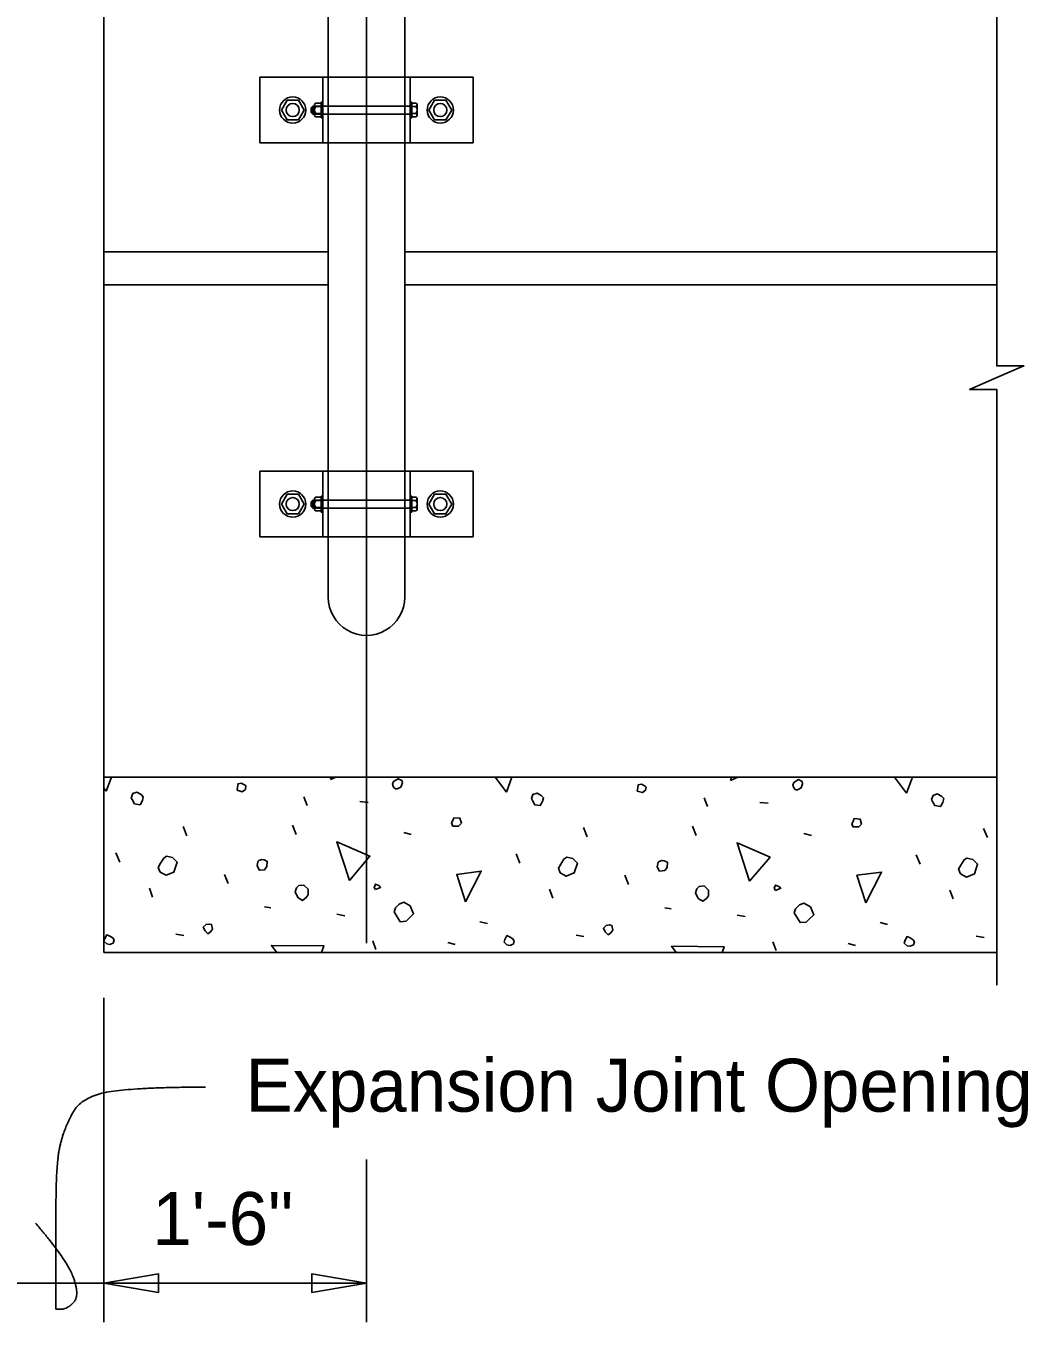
# Model space of a CAD drawing. Extents: x 0 to 41.2, y 0 to 26.
# Drawn here: x 27.279 to 31.095, y 12.062 to 16.996 of the extents above; entities that cross this region are included whole.
import ezdxf

# ---------------------------------------------------------------- set-up
doc = ezdxf.new("R2010")
doc.units = 0
for name, color, linetype in [('CL_Major', 7, 'Continuous'), ('Dimension', 7, 'Continuous'), ('Miscellaneous', 7, 'Continuous'), ('SteelMisc', 7, 'Continuous'), ('SteelMisc_h', 7, 'Continuous'), ('SupstrConc', 7, 'Continuous'), ('TextStructures', 7, 'Continuous')]:
    doc.layers.add(name, color=color, linetype=linetype)

msp = doc.modelspace()

# ---------------------------------------------------------------- linework, layer by layer
at = {"layer": 'CL_Major'}
for p, q in [((28.5763, 25.5043), (28.5763, 13.5039)), ((28.5763, 12.6814), (28.5763, 12.062))]:
    msp.add_line(p, q, dxfattribs=at)
at = {"layer": 'Dimension'}
for p, q in [((27.5763, 13.2961), (27.5763, 12.062)), ((28.5763, 12.21), (26.2429, 12.21))]:
    msp.add_line(p, q, dxfattribs=at)
msp.add_lwpolyline([(30.9761, 17.1361), (30.9761, 15.7022), (31.0795, 15.7022), (30.9761, 15.6572), (30.8728, 15.6122), (30.9761, 15.6122), (30.9761, 13.3448)], dxfattribs=at)
for points in [[(27.5762, 12.2101), (27.7845, 12.1748), (27.7845, 12.2454)], [(28.5762, 12.2101), (28.368, 12.2454), (28.368, 12.1748)]]:
    msp.add_lwpolyline(points, close=True, dxfattribs=at)
msp.add_open_spline([(27.3159, 12.4385), (27.434, 12.3022), (27.4854, 12.1629), (27.437, 12.1114), (27.3939, 12.1114), (27.3939, 12.1114), (27.3939, 12.3628), (27.3939, 12.6656), (27.4249, 12.8019), (27.4975, 12.926), (27.7306, 12.9563), (27.9637, 12.9563)], degree=2, dxfattribs=at)
at = {"layer": 'Miscellaneous'}
for p, q in [((28.3687, 16.6691), (28.3687, 16.6812)), ((28.3744, 16.6691), (28.3744, 16.6812)), ((28.3687, 15.1691), (28.3687, 15.1812)), ((28.3744, 15.1691), (28.3744, 15.1812)), ((29.525, 14.1361), (29.5261, 14.1359)), ((28.3505, 14.0281), (28.3382, 14.0617)), ((28.5503, 14.044), (28.5821, 14.0404)), ((29.8743, 14.0245), (29.862, 14.0581)), ((30.0741, 14.0404), (30.1059, 14.0369)), ((27.8927, 13.9132), (27.8785, 13.9485)), ((28.3081, 13.9185), (28.294, 13.9538)), ((28.7182, 13.9255), (28.7465, 13.9185)), ((29.4165, 13.9096), (29.4024, 13.945)), ((29.8319, 13.9149), (29.8178, 13.9503)), ((30.242, 13.922), (30.2703, 13.9149)), ((30.9403, 13.9061), (30.9262, 13.9414)), ((27.6364, 13.8124), (27.6222, 13.8478)), ((29.1602, 13.8089), (29.146, 13.8442)), ((30.684, 13.8053), (30.6698, 13.8407)), ((28.05, 13.7311), (28.0359, 13.7664)), ((29.5738, 13.7275), (29.5597, 13.7629)), ((27.7619, 13.6798), (27.7495, 13.7134)), ((29.2857, 13.6763), (29.2733, 13.7099)), ((30.8095, 13.6727), (30.7971, 13.7063)), ((28.1879, 13.6427), (28.2126, 13.6392)), ((29.7117, 13.6392), (29.7365, 13.6356)), ((28.4637, 13.6144), (28.4937, 13.6091)), ((29.0081, 13.5861), (29.0364, 13.5791)), ((29.9875, 13.6109), (30.0175, 13.6056)), ((30.532, 13.5826), (30.5602, 13.5755)), ((27.8503, 13.5384), (27.8803, 13.5331)), ((29.3741, 13.5349), (29.4041, 13.5296)), ((30.8979, 13.5313), (30.9279, 13.526)), ((28.6122, 13.4801), (28.5998, 13.5136)), ((28.8862, 13.5066), (28.9145, 13.4995)), ((30.136, 13.4765), (30.1236, 13.5101)), ((30.41, 13.503), (30.4383, 13.496))]:
    msp.add_line(p, q, dxfattribs=at)
for points in [[(27.605, 14.1361), (27.5851, 14.0829)], [(28.0836, 14.0864), (28.103, 14.0811), (28.1154, 14.0899), (28.1172, 14.1023), (28.1137, 14.1058), (28.0995, 14.1129), (28.0871, 14.1112), (28.0854, 14.0988), (28.0836, 14.0864)], [(28.4389, 14.1271), (28.4417, 14.1361)], [(28.4591, 14.1361), (28.4389, 14.1271)], [(28.6864, 14.0917), (28.6935, 14.0917), (28.7076, 14.0988), (28.7129, 14.1147), (28.7112, 14.1235), (28.697, 14.1306), (28.6793, 14.12), (28.6758, 14.1094), (28.6793, 14.0988), (28.6864, 14.0917)], [(29.1089, 14.0793), (29.0657, 14.1361)], [(29.1301, 14.1361), (29.1089, 14.0793)], [(29.9627, 14.1235), (29.9666, 14.1361)], [(29.9908, 14.1361), (29.9627, 14.1235)], [(30.2102, 14.0882), (30.2173, 14.0882), (30.2314, 14.0952), (30.2367, 14.1112), (30.235, 14.12), (30.2208, 14.1271), (30.2032, 14.1165), (30.1996, 14.1058), (30.2032, 14.0952), (30.2102, 14.0882)], [(30.6327, 14.0758), (30.5869, 14.1361)], [(30.6553, 14.1361), (30.6327, 14.0758)], [(27.5851, 14.0829), (27.5763, 14.0945)], [(27.6841, 14.051), (27.6929, 14.0351), (27.7141, 14.0316), (27.723, 14.0475), (27.7265, 14.0617), (27.7177, 14.0705), (27.7018, 14.0793), (27.6859, 14.074), (27.6805, 14.0581), (27.6841, 14.051)], [(29.2079, 14.0475), (29.2167, 14.0316), (29.238, 14.0281), (29.2468, 14.044), (29.2503, 14.0581), (29.2415, 14.067), (29.2256, 14.0758), (29.2097, 14.0705), (29.2044, 14.0546), (29.2079, 14.0475)], [(29.6074, 14.0829), (29.6269, 14.0776), (29.6392, 14.0864), (29.641, 14.0988), (29.6375, 14.1023), (29.6233, 14.1094), (29.611, 14.1076), (29.6092, 14.0952), (29.6074, 14.0829)], [(30.7317, 14.044), (30.7406, 14.0281), (30.7618, 14.0245), (30.7706, 14.0404), (30.7741, 14.0546), (30.7653, 14.0634), (30.7494, 14.0723), (30.7335, 14.067), (30.7282, 14.051), (30.7317, 14.044)], [(28.9056, 13.9503), (28.9268, 13.9503), (28.9374, 13.9609), (28.9321, 13.9803), (28.9091, 13.9821), (28.9056, 13.9715), (28.9003, 13.9627), (28.9056, 13.9503), (28.9021, 13.9538)], [(30.4294, 13.9467), (30.4506, 13.9467), (30.4612, 13.9574), (30.4559, 13.9768), (30.433, 13.9786), (30.4294, 13.968), (30.4241, 13.9591), (30.4294, 13.9467), (30.4259, 13.9503)], [(28.5114, 13.7435), (28.4637, 13.8902), (28.5892, 13.8354), (28.5114, 13.7435)], [(30.0352, 13.7399), (29.9875, 13.8866), (30.113, 13.8318), (30.0352, 13.7399)], [(27.7902, 13.7753), (27.8131, 13.7629), (27.8432, 13.7753), (27.8556, 13.8124), (27.8379, 13.8301), (27.8149, 13.8354), (27.8043, 13.8283), (27.7919, 13.8089), (27.7831, 13.793), (27.7902, 13.7753)], [(28.1596, 13.7983), (28.1685, 13.7823), (28.1879, 13.7841), (28.1967, 13.7965), (28.1985, 13.8159), (28.1861, 13.8212), (28.1773, 13.823), (28.1667, 13.8195), (28.1631, 13.8159), (28.1596, 13.7983)], [(29.314, 13.7717), (29.3369, 13.7594), (29.367, 13.7717), (29.3794, 13.8089), (29.3617, 13.8265), (29.3387, 13.8318), (29.3281, 13.8248), (29.3157, 13.8053), (29.3069, 13.7894), (29.314, 13.7717)], [(29.6834, 13.7947), (29.6923, 13.7788), (29.7117, 13.7806), (29.7206, 13.793), (29.7223, 13.8124), (29.7099, 13.8177), (29.7011, 13.8195), (29.6905, 13.8159), (29.687, 13.8124), (29.6834, 13.7947)], [(30.8378, 13.7682), (30.8608, 13.7558), (30.8908, 13.7682), (30.9032, 13.8053), (30.8855, 13.823), (30.8625, 13.8283), (30.8519, 13.8212), (30.8395, 13.8018), (30.8307, 13.7859), (30.8378, 13.7682)], [(28.9533, 13.6621), (28.9198, 13.7664), (29.0134, 13.7788), (28.9533, 13.6621)], [(30.4772, 13.6586), (30.4436, 13.7629), (30.5373, 13.7753), (30.4772, 13.6586)], [(28.3046, 13.6993), (28.3152, 13.678), (28.3329, 13.6674), (28.347, 13.678), (28.3541, 13.6887), (28.3541, 13.7099), (28.3382, 13.7258), (28.3187, 13.724), (28.3099, 13.7152), (28.3046, 13.6993)], [(28.6104, 13.7081), (28.6298, 13.7169), (28.6228, 13.724), (28.6104, 13.7293), (28.6051, 13.7169), (28.6104, 13.7081)], [(29.8284, 13.6957), (29.839, 13.6745), (29.8567, 13.6639), (29.8708, 13.6745), (29.8779, 13.6851), (29.8779, 13.7063), (29.862, 13.7222), (29.8425, 13.7205), (29.8337, 13.7116), (29.8284, 13.6957)], [(30.1342, 13.7046), (30.1537, 13.7134), (30.1466, 13.7205), (30.1342, 13.7258), (30.1289, 13.7134), (30.1342, 13.7046)], [(28.6811, 13.6232), (28.7041, 13.5861), (28.7271, 13.5879), (28.7359, 13.5967), (28.7554, 13.6162), (28.743, 13.6462), (28.7182, 13.6604), (28.7006, 13.6533), (28.6864, 13.6392), (28.6811, 13.6232)], [(30.2049, 13.6197), (30.2279, 13.5826), (30.2509, 13.5844), (30.2597, 13.5932), (30.2792, 13.6126), (30.2668, 13.6427), (30.242, 13.6568), (30.2244, 13.6498), (30.2102, 13.6356), (30.2049, 13.6197)], [(27.9616, 13.5508), (27.9722, 13.5402), (27.9828, 13.5472), (27.9899, 13.5578), (27.9864, 13.5755), (27.9775, 13.5773), (27.9652, 13.5755), (27.9546, 13.5649), (27.9616, 13.5508)], [(29.4854, 13.5472), (29.496, 13.5366), (29.5067, 13.5437), (29.5137, 13.5543), (29.5102, 13.572), (29.5013, 13.5738), (29.489, 13.572), (29.4784, 13.5614), (29.4854, 13.5472)], [(27.5869, 13.5013), (27.5992, 13.4995), (27.6116, 13.5048), (27.6151, 13.5154), (27.6098, 13.5243), (27.5992, 13.5313), (27.5869, 13.5366), (27.5798, 13.5225), (27.5763, 13.5119), (27.5869, 13.5013)], [(29.1107, 13.4977), (29.123, 13.496), (29.1354, 13.5013), (29.139, 13.5119), (29.1337, 13.5207), (29.123, 13.5278), (29.1107, 13.5331), (29.1036, 13.5189), (29.1001, 13.5083), (29.1107, 13.4977)], [(30.6345, 13.4942), (30.6469, 13.4924), (30.6592, 13.4977), (30.6628, 13.5083), (30.6575, 13.5172), (30.6469, 13.5243), (30.6345, 13.5296), (30.6274, 13.5154), (30.6239, 13.5048), (30.6345, 13.4942)], [(28.2346, 13.4695), (28.2144, 13.496), (28.4142, 13.4942), (28.4049, 13.4695)], [(29.7557, 13.4695), (29.7382, 13.4924), (29.938, 13.4907), (29.9301, 13.4695)]]:
    msp.add_lwpolyline(points, dxfattribs=at)
at = {"layer": 'SteelMisc'}
for p, q in [((28.4305, 16.801), (28.4305, 17.2769)), ((28.7221, 16.801), (28.7221, 17.2769)), ((28.1703, 16.801), (28.9823, 16.801)), ((28.1703, 16.551), (28.1703, 16.801)), ((28.4096, 16.801), (28.4096, 16.551)), ((28.743, 16.801), (28.743, 16.551)), ((28.9823, 16.801), (28.9823, 16.551)), ((28.3659, 16.684), (28.3715, 16.6906)), ((28.3659, 16.6663), (28.3659, 16.684)), ((28.3715, 16.6906), (28.3781, 16.6906)), ((28.3715, 16.6607), (28.3715, 16.6906)), ((28.3781, 16.6939), (28.3781, 16.6582)), ((28.3828, 16.689), (28.4031, 16.689)), ((28.383, 16.702), (28.4031, 16.702)), ((28.4031, 16.7063), (28.4031, 16.6457)), ((28.4031, 16.7063), (28.4096, 16.7063)), ((28.4031, 16.702), (28.4031, 16.65)), ((28.7492, 16.7063), (28.7432, 16.7063)), ((28.7492, 16.7063), (28.7492, 16.6457)), ((28.7639, 16.702), (28.7492, 16.702)), ((28.7641, 16.689), (28.7492, 16.689)), ((28.769, 16.6566), (28.769, 16.6955)), ((28.3659, 16.6663), (28.3715, 16.6607)), ((28.3715, 16.6607), (28.3781, 16.6607)), ((28.3828, 16.6631), (28.4031, 16.6631)), ((28.3831, 16.65), (28.4031, 16.65)), ((28.4031, 16.6457), (28.4096, 16.6457)), ((28.7492, 16.6457), (28.7432, 16.6457)), ((28.7641, 16.663), (28.7492, 16.663)), ((28.7639, 16.65), (28.7492, 16.65)), ((28.9823, 16.551), (28.1703, 16.551)), ((28.4305, 16.551), (28.4305, 15.301)), ((28.7221, 16.551), (28.7221, 15.301)), ((28.1703, 15.301), (28.9823, 15.301)), ((28.1703, 15.051), (28.1703, 15.301)), ((28.4096, 15.301), (28.4096, 15.051)), ((28.743, 15.301), (28.743, 15.051)), ((28.9823, 15.301), (28.9823, 15.051)), ((28.383, 15.202), (28.4031, 15.202)), ((28.4031, 15.2063), (28.4031, 15.1457)), ((28.4031, 15.2063), (28.4096, 15.2063)), ((28.4031, 15.202), (28.4031, 15.15)), ((28.7492, 15.2063), (28.7432, 15.2063)), ((28.7492, 15.2063), (28.7492, 15.1457)), ((28.7639, 15.202), (28.7492, 15.202)), ((28.3659, 15.184), (28.3715, 15.1906)), ((28.3659, 15.1663), (28.3659, 15.184)), ((28.3659, 15.1663), (28.3715, 15.1607)), ((28.3715, 15.1906), (28.3781, 15.1906)), ((28.3715, 15.1607), (28.3715, 15.1906)), ((28.3715, 15.1607), (28.3781, 15.1607)), ((28.3781, 15.1939), (28.3781, 15.1582)), ((28.3828, 15.189), (28.4031, 15.189)), ((28.3828, 15.1631), (28.4031, 15.1631)), ((28.3831, 15.15), (28.4031, 15.15)), ((28.7641, 15.189), (28.7492, 15.189)), ((28.7641, 15.163), (28.7492, 15.163)), ((28.7639, 15.15), (28.7492, 15.15)), ((28.769, 15.1566), (28.769, 15.1955)), ((28.4031, 15.1457), (28.4096, 15.1457)), ((28.7492, 15.1457), (28.7432, 15.1457)), ((28.9823, 15.051), (28.1703, 15.051)), ((28.4303, 15.051), (28.4303, 14.8218)), ((28.722, 14.8218), (28.722, 15.051))]:
    msp.add_line(p, q, dxfattribs=at)
for points in [[(28.2736, 16.7135), (28.317, 16.7135), (28.3386, 16.676), (28.317, 16.6385), (28.2736, 16.6385), (28.252, 16.676)], [(28.8356, 16.7135), (28.8789, 16.7135), (28.9006, 16.676), (28.8789, 16.6385), (28.8356, 16.6385), (28.8139, 16.676)], [(28.2736, 15.2135), (28.317, 15.2135), (28.3386, 15.176), (28.317, 15.1385), (28.2736, 15.1385), (28.252, 15.176)], [(28.8356, 15.2135), (28.8789, 15.2135), (28.9006, 15.176), (28.8789, 15.1385), (28.8356, 15.1385), (28.8139, 15.176)]]:
    msp.add_lwpolyline(points, close=True, dxfattribs=at)
for centre, radius in [((28.2953, 16.676), 0.05), ((28.2953, 16.676), 0.025), ((28.8573, 16.676), 0.05), ((28.8573, 16.676), 0.025), ((28.2953, 15.176), 0.05), ((28.2953, 15.176), 0.025), ((28.8573, 15.176), 0.05), ((28.8573, 15.176), 0.025)]:
    msp.add_circle(centre, radius, dxfattribs=at)
for centre, radius, start, end in [((28.3846, 16.6955), 0.00674, 104.4891, 254.1889), ((28.3975, 16.676), 0.0196, 138.628, 221.372), ((28.7622, 16.6955), 0.00673, 285.7823, 75.5404), ((28.7493, 16.676), 0.0196, 318.628, 41.372), ((28.3846, 16.6565), 0.00673, 105.7823, 255.5404), ((28.7622, 16.6565), 0.00674, 284.4891, 74.1889), ((28.3846, 15.1955), 0.00674, 104.4891, 254.1889), ((28.7622, 15.1955), 0.00673, 285.7823, 75.5404), ((28.3975, 15.176), 0.0196, 138.628, 221.372), ((28.3846, 15.1565), 0.00673, 105.7823, 255.5404), ((28.7622, 15.1565), 0.00674, 284.4891, 74.1889), ((28.7493, 15.176), 0.0196, 318.628, 41.372)]:
    msp.add_arc(centre, radius, start, end, dxfattribs=at)
msp.add_ellipse((28.5763, 14.8218), major_axis=(0, 0.1458), ratio=0.999499, start_param=1.570796, end_param=4.712389, dxfattribs=at)
at = {"layer": 'SteelMisc_h'}
for p, q in [((28.4305, 16.801), (28.4305, 16.551)), ((28.7221, 16.801), (28.7221, 16.551)), ((28.743, 16.6906), (28.3781, 16.6906)), ((28.3781, 16.6607), (28.743, 16.6607)), ((28.4305, 15.301), (28.4305, 15.051)), ((28.7221, 15.301), (28.7221, 15.051)), ((28.743, 15.1906), (28.3781, 15.1906)), ((28.3781, 15.1607), (28.743, 15.1607))]:
    msp.add_line(p, q, dxfattribs=at)
at = {"layer": 'SupstrConc'}
for p, q in [((27.5763, 17.1361), (27.5763, 13.4695)), ((27.5763, 16.1361), (28.4305, 16.1361)), ((28.7221, 16.1361), (30.976, 16.1361)), ((27.5763, 16.0111), (28.4305, 16.0111)), ((28.7221, 16.0111), (30.976, 16.0111)), ((27.5763, 14.1361), (30.9761, 14.1361)), ((27.5763, 13.4695), (30.9761, 13.4695))]:
    msp.add_line(p, q, dxfattribs=at)

# ---------------------------------------------------------------- texts
at = {"layer": 'TextStructures'}
for s, p in [('Expansion Joint Opening', (28.1153, 12.863)), ('1\'-6"', (27.7605, 12.3553))]:
    msp.add_text(s, height=0.2016, dxfattribs=at).set_placement(p)

doc.saveas('drawing.dxf')
